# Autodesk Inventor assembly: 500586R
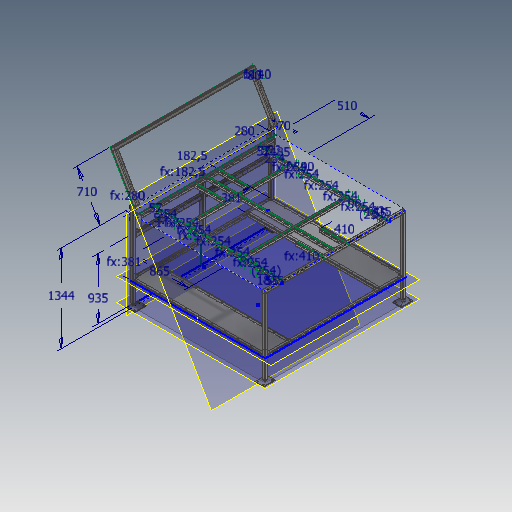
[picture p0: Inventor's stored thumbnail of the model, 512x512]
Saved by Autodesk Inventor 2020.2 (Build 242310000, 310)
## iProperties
_SolveAssemblyDoc: Frame Generator Solve Assembly
_Version: 15.0.0
Created: 2019-10
Part Number: 500586R
Document SubType Name: Assembly
Designer: lutzd
Mass: 280839 g
Surface Area: 173396 cm^2
Volume: 40161.8 cm^3
Density: 6.9927 g/cm^3
VLDS_Profile: Default Assembly
VLDS_TimeStamp: 2016-07-29
VLDS_FailCnt: 0
VLDS_AcceptCnt: 0
Dimensions: 2297,8x1993,9x2426,7 mm
Mass: 280,839 kg
DocNumber: 500586R.iam
Folder: 01 - Themengebiete\Simplification\01 - Packaging machine\Parts\
VDS_Category: 3D Komponenten
Author: lutzd
Revision Number: -
Title: frame
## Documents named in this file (7)
- D:\07 - DEMODATEN\OTX 2019 - Dataset - UPDATE - Dez2019\Designs\07-Packing machine\500586R.iam
- D:\07 - DEMODATEN\OTX 2019 - Dataset - UPDATE - Dez2019\Designs\07-Packing machine\Parts\ADSK-014370.ipt
- D:\07 - DEMODATEN\OTX 2019 - Dataset - UPDATE - Dez2019\Designs\07-Packing machine\500586R\Frame\Frame 1572274296176.iam
- D:\07 - DEMODATEN\OTX 2019 - Dataset - UPDATE - Dez2019\Designs\07-Packing machine\Parts\ADSK-011287.ipt
- D:\07 - DEMODATEN\OTX 2019 - Dataset - UPDATE - Dez2019\Designs\07-Packing machine\Parts\ADSK-011288.ipt
- D:\07 - DEMODATEN\OTX 2019 - Dataset - UPDATE - Dez2019\Designs\07-Packing machine\Parts\ADSK-011671.ipt
- D:\07 - DEMODATEN\OTX 2019 - Dataset - UPDATE - Dez2019\Content Center Files\de-DE\ISO 10642(1)\ISO 10642 - M5x12.ipt
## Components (56 placed, 6 different names)
1. ADSK-014370:1 — Fluchtend:1, Fluchtend:2, Fluchtend:3, Fluchtend:77
2. Frame 1572274296176:1 [sub-assembly] — Passend:13, Passend:14, Fluchtend:5, Fluchtend:6, Passend:15, Passend:16, Passend:17, Passend:18
3. ADSK-011287:1 — Fluchtend:1, Fluchtend:5
4. ADSK-011288:1 — Passend:14
5. ADSK-011287:2 — Fluchtend:2, Fluchtend:6
6. ADSK-011288:2 — Passend:13
7. ADSK-011287:3 — Fluchtend:3, Passend:17
8. ADSK-011288:3 — Passend:16
9. ADSK-011287:4 — Passend:18, Fluchtend:77, Passend:77
10. ADSK-011288:4 — Passend:15, Passend:77
11. ADSK-011671:2
12. ADSK-011671:1
13. ISO 10642 M5x12:1
14. ISO 10642 M5x12:2
15. ISO 10642 M5x12:3
16. ISO 10642 M5x12:4
17. ISO 10642 M5x12:5
18. ISO 10642 M5x12:6
19. ISO 10642 M5x12:7
20. ISO 10642 M5x12:8
21. ISO 10642 M5x12:9
22. ISO 10642 M5x12:10
23. ISO 10642 M5x12:11
24. ISO 10642 M5x12:12
25. ISO 10642 M5x12:13
26. ISO 10642 M5x12:14
27. ISO 10642 M5x12:15
28. ISO 10642 M5x12:16
29. ISO 10642 M5x12:17
30. ISO 10642 M5x12:18
31. ISO 10642 M5x12:19
32. ISO 10642 M5x12:20
33. ISO 10642 M5x12:21
34. ISO 10642 M5x12:22
35. ISO 10642 M5x12:23
36. ISO 10642 M5x12:24
37. ISO 10642 M5x12:25
38. ISO 10642 M5x12:26
39. ISO 10642 M5x12:27
40. ISO 10642 M5x12:28
41. ISO 10642 M5x12:29
42. ISO 10642 M5x12:30
43. ISO 10642 M5x12:31
44. ISO 10642 M5x12:32
45. ISO 10642 M5x12:33
46. ISO 10642 M5x12:34
47. ISO 10642 M5x12:35
48. ISO 10642 M5x12:36
49. ISO 10642 M5x12:37
50. ISO 10642 M5x12:38
51. ISO 10642 M5x12:39
52. ISO 10642 M5x12:40
53. ISO 10642 M5x12:41
54. ISO 10642 M5x12:42
55. ISO 10642 M5x12:43
56. ISO 10642 M5x12:44
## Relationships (13: Mate 7, Flush 6)
- Fluchtend:1 [Flush]: ADSK-014370:1 ↔ ADSK-011287:1
- Fluchtend:2 [Flush]: ADSK-014370:1 ↔ ADSK-011287:2
- Fluchtend:3 [Flush]: ADSK-014370:1 ↔ ADSK-011287:3
- Passend:13 [Mate]: Frame 1572274296176:1 ↔ ADSK-011288:2
- Passend:14 [Mate]: Frame 1572274296176:1 ↔ ADSK-011288:1
- Fluchtend:5 [Flush]: Frame 1572274296176:1 ↔ ADSK-011287:1
- Fluchtend:6 [Flush]: Frame 1572274296176:1 ↔ ADSK-011287:2
- Passend:15 [Mate]: Frame 1572274296176:1 ↔ ADSK-011288:4
- Passend:16 [Mate]: Frame 1572274296176:1 ↔ ADSK-011288:3
- Passend:17 [Mate]: Frame 1572274296176:1 ↔ ADSK-011287:3
- Passend:18 [Mate]: Frame 1572274296176:1 ↔ ADSK-011287:4
- Fluchtend:77 [Flush]: ADSK-014370:1 ↔ ADSK-011287:4
- Passend:77 [Mate]: ADSK-011287:4 ↔ ADSK-011288:4
## Named parameters: d70_d50 = 45 mm, d71_d47 = 0, d72_d49 = 0, d3_d70_d50 = 45 mm, d4_d71_d47 = 0, d5_d72_d49 = 0, d11_d46 = 0
